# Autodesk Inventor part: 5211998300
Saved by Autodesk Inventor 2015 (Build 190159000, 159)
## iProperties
Created: 2020-07
Part Number: 5211998300
Checked By: TraceParts S.A.
Material: Generic
Catalog Web Link: www.traceparts.com
Document SubType Name: Modeling
Designer: TraceParts
Density: 1 g/cm^3
Appearance: Default
Company: TraceParts S.A.
Author: TraceParts
REFERENCE: 5211998300
DESIGN: TDM-200 (127V 60) BRA RZ - 5211998300
SUPPLIER: Soler & Palau
TraceParts.PartNumber: 10-20122018-119657
TraceParts.PartTitle: TDM
TraceParts.InstanceId: 10-20122018-1196576ONWRF8OKHF26MFB0F0AVIUS8
TraceParts.PartStatus: Published
TraceParts.PartVersion: 1.0.2
TRACEPARTS: TRACEPARTS
TraceParts.PartLanguage: en
TraceParts.ClassPath: SOLER_PALAU:10-20122018-119657
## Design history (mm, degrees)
feature "5211998300"
body "Solid1"
